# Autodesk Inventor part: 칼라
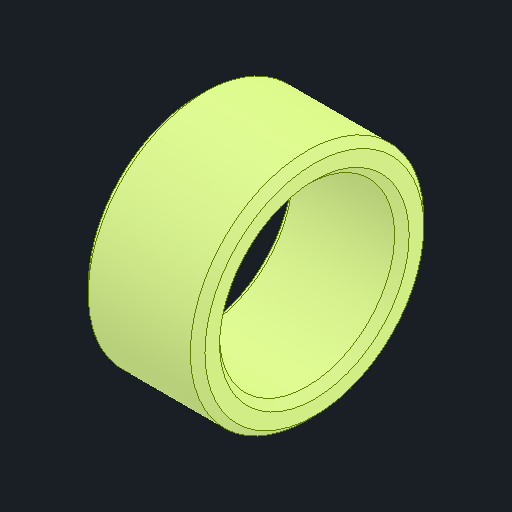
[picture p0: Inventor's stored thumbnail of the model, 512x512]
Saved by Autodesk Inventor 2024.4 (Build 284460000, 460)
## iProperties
Created: 2026-03
Part Number: 칼라
Material: 강철, 연강
Document SubType Name: Modeling
Designer: user
Density: 7.85 g/cm^3
Appearance: 기본값
Author: jhkim
Sending System: Autodesk Inventor 2026
Preprocessor: ST-DEVELOPER v20.1
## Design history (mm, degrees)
feature "솔리드1"
node "솔리드2"
